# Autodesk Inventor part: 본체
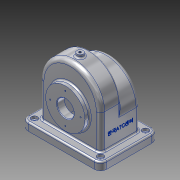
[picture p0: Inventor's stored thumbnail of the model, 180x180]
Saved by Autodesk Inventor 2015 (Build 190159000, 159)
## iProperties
Created: 2017-11
Part Number: 본체
Material: 알루미늄 6061
Document SubType Name: Modeling
Designer: 2-PC07
Density: 2.7 g/cm^3
Appearance: 알루미늄 - 평지
Mass: 1076.56 g
Surface Area: 1180.5 cm^2
Volume: 398.727 cm^3
Author: 2-PC07
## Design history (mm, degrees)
sketch "스케치1"
  geometry: L1 (-58, 0)-(-58, -80); L2 (-58, -80)-(58, -80); L3 (58, -80)-(58, 0); A1 r 58 centre (0, 0) between (58, 0) and (-58, 0); 1 further point
  constraints: 6 end point, 2 point on circle, 2 tangent, 2 vertical, 1 centre point, 1 coincident, 1 perpendicular
  dimensions: "d0" = 116 diameter of A1; "d1" = 80 distance of L2.end L3.end
extrude "돌출1" new body sketch "스케치1" distance "d2" = 38; taper "d3" = 0 deg
sketch "스케치2"
  geometry: L1 (-58, 23)-(-58, 80); L2 (-58, 80)-(58, 80); L3 (58, 80)-(58, 23); L4 (58, 0)-(58, 80) reference; A1 r 58 centre (0, 23) between (-58, 23) and (58, 23); 1 further point
  constraints: 6 end point, 2 point on circle, 1 centre point, 1 perpendicular, 1 point on line, 1 tangent, 1 vertical
  dimensions: "d4" = 116 diameter of A1; "d5" = 57 distance of L1.start L1.end
extrude "돌출2" join sketch "스케치2" distance "d6" = 38; taper "d7" = 0 deg
feature "쉘1" dims "d8" = 5
sketch "스케치3"
  geometry: L1 (-58, -80)-(58, -80) reference; C1 r 37.5 at (0, -15); 1 further point
  constraints: 1 centre point, 1 vertical alignment
  dimensions: "d9" = 75 diameter of C1; "d10" = 65 distance from line of L1 C1.centre
extrude "돌출3" join sketch "스케치3" distance "d11" = 9; taper "d12" = 0 deg
sketch "스케치4"
  geometry: L1 (58, 80)-(-58, 80) reference; C1 r 31 at (0, 15); 1 further point
  constraints: 1 centre point, 1 vertical alignment
  dimensions: "d13" = 62 diameter of C1; "d14" = 65 distance from line of L1 C1.centre
extrude "돌출4" join sketch "스케치4" distance "d15" = 10; taper "d16" = 0 deg
sketch "스케치5"
  geometry: C1 r 16 at (0, 0); C2 r 37.5 at (0, 0) reference; 1 further point
  constraints: 1 centre point, 1 concentric
  dimensions: "d17" = 32 diameter of C1
extrude "돌출5" cut sketch "스케치5" stored distance "d18" = 10; taper "d19" = 0 deg
sketch "스케치6"
  geometry: L1 (-17, -17)-(133, -17); L2 (133, -17)-(133, 93); L3 (133, 93)-(-17, 93); L4 (-17, 93)-(-17, -17); L5 (116, 38)-(0, 38) reference; L6 (116, 0)-(0, 0) reference; L7 (0, 0)-(116, 0); L8 (116, 0)-(116, 76); L9 (116, 76)-(0, 76); L10 (0, 76)-(0, 0); L11 (0, 76)-(116, 76) reference; L12 (116, 0)-(116, 76) reference; 3 further points
  constraints: 16 end point, 4 parallel, 2 collinear, 2 horizontal, 2 midpoint, 2 perpendicular, 1 vertical alignment
  dimensions: "d20" = 110 distance of L1.end L2.end; "d21" = 150 distance of L2.end L3.end; "d22" = 55 distance between parallel lines of L5 L1
extrude "돌출6" join sketch "스케치6" distance "d23" = 15; taper "d24" = 0 deg
fillet "모깎기1" dims "d25" = 12
sketch "스케치7"
  geometry: C1 r 6 at (5, -5); C2 r 6 at (5, 81); C3 r 6 at (-121, 81); C4 r 6 at (-121, -5); A1 r 12 centre (5, 81) between (17, 81) and (5, 93) reference; A2 r 12 centre (-121, 81) between (-121, 93) and (-133, 81) reference; A3 r 12 centre (-121, -5) between (-133, -5) and (-121, -17) reference; A4 r 12 centre (5, -5) between (5, -17) and (17, -5) reference; 1 further point
  constraints: 4 centre point, 4 concentric
  dimensions: "d26" = 12 diameter of C1; "d27" = 12 diameter of C2; "d28" = 12 diameter of C3; "d29" = 12 diameter of C4
extrude "돌출7" cut sketch "스케치7" distance "d30" = 5; taper "d31" = 0 deg
sketch "스케치8"
  geometry: L1 (0, 29)-(0, -29); L2 (-29, 0)-(29, 0); C1 r 37.5 at (0, 0) reference; A1 r 29 centre (0, 0) between (0, 29) and (0, -29); 5 further points
  constraints: 4 coincident, 4 end point, 4 point on circle, 1 centre point, 1 concentric, 1 perpendicular, 1 vertical
  dimensions: "d32" = 58 diameter of A1; "d33" = 58 distance of L1.start L1.end; "d34" = 58 distance of L2.start L2.end
sketch "스케치9"
  geometry: C1 r 2.5 at (0, 0); C2 r 2.5 at (0, 86); C3 r 2.5 at (-126, 86); C4 r 2.5 at (-126, 0); C5 r 6 at (0, 86) reference; C6 r 6 at (0, 0) reference; C7 r 6 at (-126, 86) reference; C8 r 6 at (-126, 0) reference; 1 further point
  constraints: 4 centre point, 4 concentric
  dimensions: "d35" = 5 diameter of C1; "d36" = 5 diameter of C2; "d37" = 5 diameter of C3; "d38" = 5 diameter of C4
extrude "돌출8" cut sketch "스케치9" distance "d39" = 5; taper "d40" = 0 deg
fillet "모깎기2" dims "d41" = 8
fillet "모깎기3" dims "d42" = 3
fillet "모깎기4" dims "d43" = 3
fillet "모깎기5" dims "d44" = 3
chamfer "모따기1" distance "d45" = 1; stored, may be unused: second distance "d46" = 2, angle "d47" = 45 deg
node "작업 평면1"
sketch "스케치10"
  geometry: L1 (113, -93)-(13, -93) reference; C1 r 6 at (63, -74); 1 further point
  constraints: 1 centre point, 1 vertical alignment
  dimensions: "d49" = 12 diameter of C1; "d50" = 19 distance from line of C1.centre L1
extrude "돌출9" join sketch "스케치10" stored distance "d51" = 5; taper "d52" = 0 deg
fillet "모깎기6" dims "d53" = 3
sketch "스케치12"
  geometry: L1 (18, 73)-(18, -13) reference; L2 (-62, -8)-(0, -8) reference; 1 further point
  constraints: 1 other
  dimensions: "d54" = 40 distance from line of L1 point (-22, 30); "d55" = 38 distance from line of point (-22, 30) L2
feature "엠보싱1" sketch "스케치12" dims "d0" = 116, "d1" = 80, "d9" = 75, "d10" = 65, "d56" = 0.5, "d57" = 0
sketch "스케치13"
  geometry: L1 (0, -26)-(0, 26); L2 (-26, 0)-(26, 0); C1 r 31 at (0, 0) reference; A1 r 26 centre (0, 0) between (0, -26) and (0, 26); 7 further points
  constraints: 5 coincident, 4 end point, 4 point on circle, 2 midpoint, 1 centre point, 1 concentric, 1 horizontal, 1 vertical
  dimensions: "d58" = 52 diameter of A1; "d59" = 52 distance of L1.start L1.end
hole "구멍1" sketch "스케치8" diameter "d63" = 2.459; stored, may be unused: countersink angle "d67" = 90 deg, drill point angle "d69" = 118 deg; dims "d64" = 6, "d65" = 4, "d66" = 2, "d68" = 8
hole "구멍2" sketch "스케치13" diameter "d70" = 2.459; stored, may be unused: countersink angle "d74" = 90 deg, drill point angle "d76" = 118 deg; dims "d71" = 6, "d72" = 4, "d73" = 2, "d75" = 8
hole "구멍3" diameter "d79" = 4.459; stored, may be unused: countersink angle "d83" = 90 deg, drill point angle "d85" = 118 deg; dims "d80" = 40, "d81" = 4, "d82" = 2, "d84" = 12.8, "d86" = 10, "d87" = 10
node "솔리드1"
other parameters: "d48" = -144
